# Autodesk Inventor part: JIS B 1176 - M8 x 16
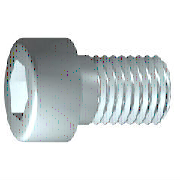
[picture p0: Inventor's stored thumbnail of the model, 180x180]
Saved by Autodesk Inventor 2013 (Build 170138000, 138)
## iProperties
Created: 2012-02
Part Number: JIS B 1176 - M8 x 16
Material: 강철, 연강
Description: 원통형 머리 캡 나사
Document SubType Name: Modeling
Standard: JIS B 1176
Designer: mdu-01
Standards Organization: JIS
Language: ko-KR
Size Designation: M8 x 16
Categories: <MemberInstance><Categories><Category DisplayName="조임쇠" InternalName="e4da775c-781d-43d5-af7c-5136215cf5a6" Mnemonic="FSTN"><Category DisplayName="볼트" InternalN
Density: 1 g/cm^3
IsCustomPart: 1
Author: mdu-01
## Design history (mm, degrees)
sketch "스케치1"
  geometry: L1 (-2, 0)-(16, 0); L2 (16, 0)-(16, 4); L3 (16, 4)-(3.125, 4); L4 (3.125, 4)-(2.358, 4); L5 (2.358, 4)-(0, 4); L6 (0, 4)-(0, 6.5); L7 (0, 6.5)-(-8, 6.5); L8 (-8, 6.5)-(-8, 3.464); L9 (-8, 3.464)-(-4, 3.464); L10 (-4, 3.464)-(-2, 0); L11 (-12.8, 0)-(20.8, 0) reference; L12 (0, -1.3)-(0, 7.8) reference; L13 (3.125, 4)-(0, 4)
  constraints: 22 end point, 6 parallel, 2 collinear, 2 perpendicular, 1 horizontal, 1 point on line
  dimensions: "d1" = 12.875 distance from line of L3.end L2 (= GEL); "d2" = 0.76691 distance of L4.end L3.end (computed from GAL); "d3" = 8 distance between parallel lines of L8 L6 (= KOH); "d4" = 4 distance of L8.end L9.end (= INTI); "d5" = 60 deg angle of L10 L1; "d6" = 8 diameter of L3 L1 (= GD); "d7" = 8 diameter of L5 L1 (= BDM); "d8" = 6.9282 diameter of L9 L1 (= 1.1547 x SW); "d9" = 13 diameter of L7 L1 (= KOD); "d26" = 16 distance between parallel lines of L12 L2 (= NLG)
revolve "본체" sketch "스케치1" stored, may be unused: angle "d10" = 90 deg
sketch "스케치2"
  geometry: L1 (0, -9.1)-(0, 9.1) reference; L2 (-9.1, 0)-(9.1, 0) reference; L3 (3.464, 0)-(1.732, -3); L4 (1.732, -3)-(-1.732, -3); L5 (-1.732, -3)-(-3.464, 0); L6 (-3.464, 0)-(-1.732, 3); L7 (-1.732, 3)-(1.732, 3); L8 (1.732, 3)-(3.464, 0); 2 further points
  constraints: 12 end point, 1 coincident, 1 horizontal alignment, 1 point on line, 12 other
extrude "슬롯" join sketch "스케치2" stored distance "d11" = 10; taper "d12" = 0 deg
workplane "Work Plane1"
fillet "Fillet2" dims "d30" = 0.1 (= R)
body "Solid1"
fillet "모깎기1" dims "d17" = 0.8 (= RR)
feature "스레드" dims "d13" = 12.875 (= GEL), "d14" = 0
chamfer "모따기1" distance "d15" = 0.76681 (= -0.5 x SPD + 0.5 x GD); stored, may be unused: second distance "d16" = 0.76681 (= GUL), angle "d27" = 45 deg
other parameters: "GD" = 8 (= NND) [user parameter; used in 2 equation terms], "NLG" = 16 [user parameter; used in 1 equation term], "GEL" = 12.875 [user parameter; used in 2 equation terms], "KOD" = 13 [user parameter; used in 1 equation term], "KOH" = 8 [user parameter; used in 1 equation term], "INTI" = 4 [user parameter; used in 1 equation term], "GAL" = 0.76681 (= 0.61345 x PTC) [user parameter; used in 1 equation term], "GUL" = 0.76681 (= 0.61345 x PTC) [user parameter; used in 1 equation term], "BDM" = 8 (= NND) [user parameter; used in 1 equation term], "SW" = 6 [user parameter; used in 2 equation terms], "RR" = 0.8 [user parameter; used in 1 equation term], "SPD" = 6.46637 (= NND - 1.2269 x PTC) [user parameter; used in 1 equation term], "d19" = 0, "d28" = 0, "d29" = 0, "R" = 0.1 [user parameter; used in 1 equation term], "PHH" = 0.4 [user parameter], "GD1" = 6.46637 (= THREADDIA - 1.2269 x PTC) [user parameter], "THREADDIA" = 8 [user parameter; used in 1 equation term], "FAWI" = 45 deg [user parameter], "TPU" = 8 (computed from PTC) [user parameter], "PTC" = 1.25 [user parameter; used in 5 equation terms], "NND" = 8 [user parameter; used in 3 equation terms], "TOA" = 30 deg [user parameter], "E0" = 6.93 (= 1.155 x SW) [user parameter]
